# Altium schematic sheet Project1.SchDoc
size B; SheetNumber: 0; SheetTotal: 0
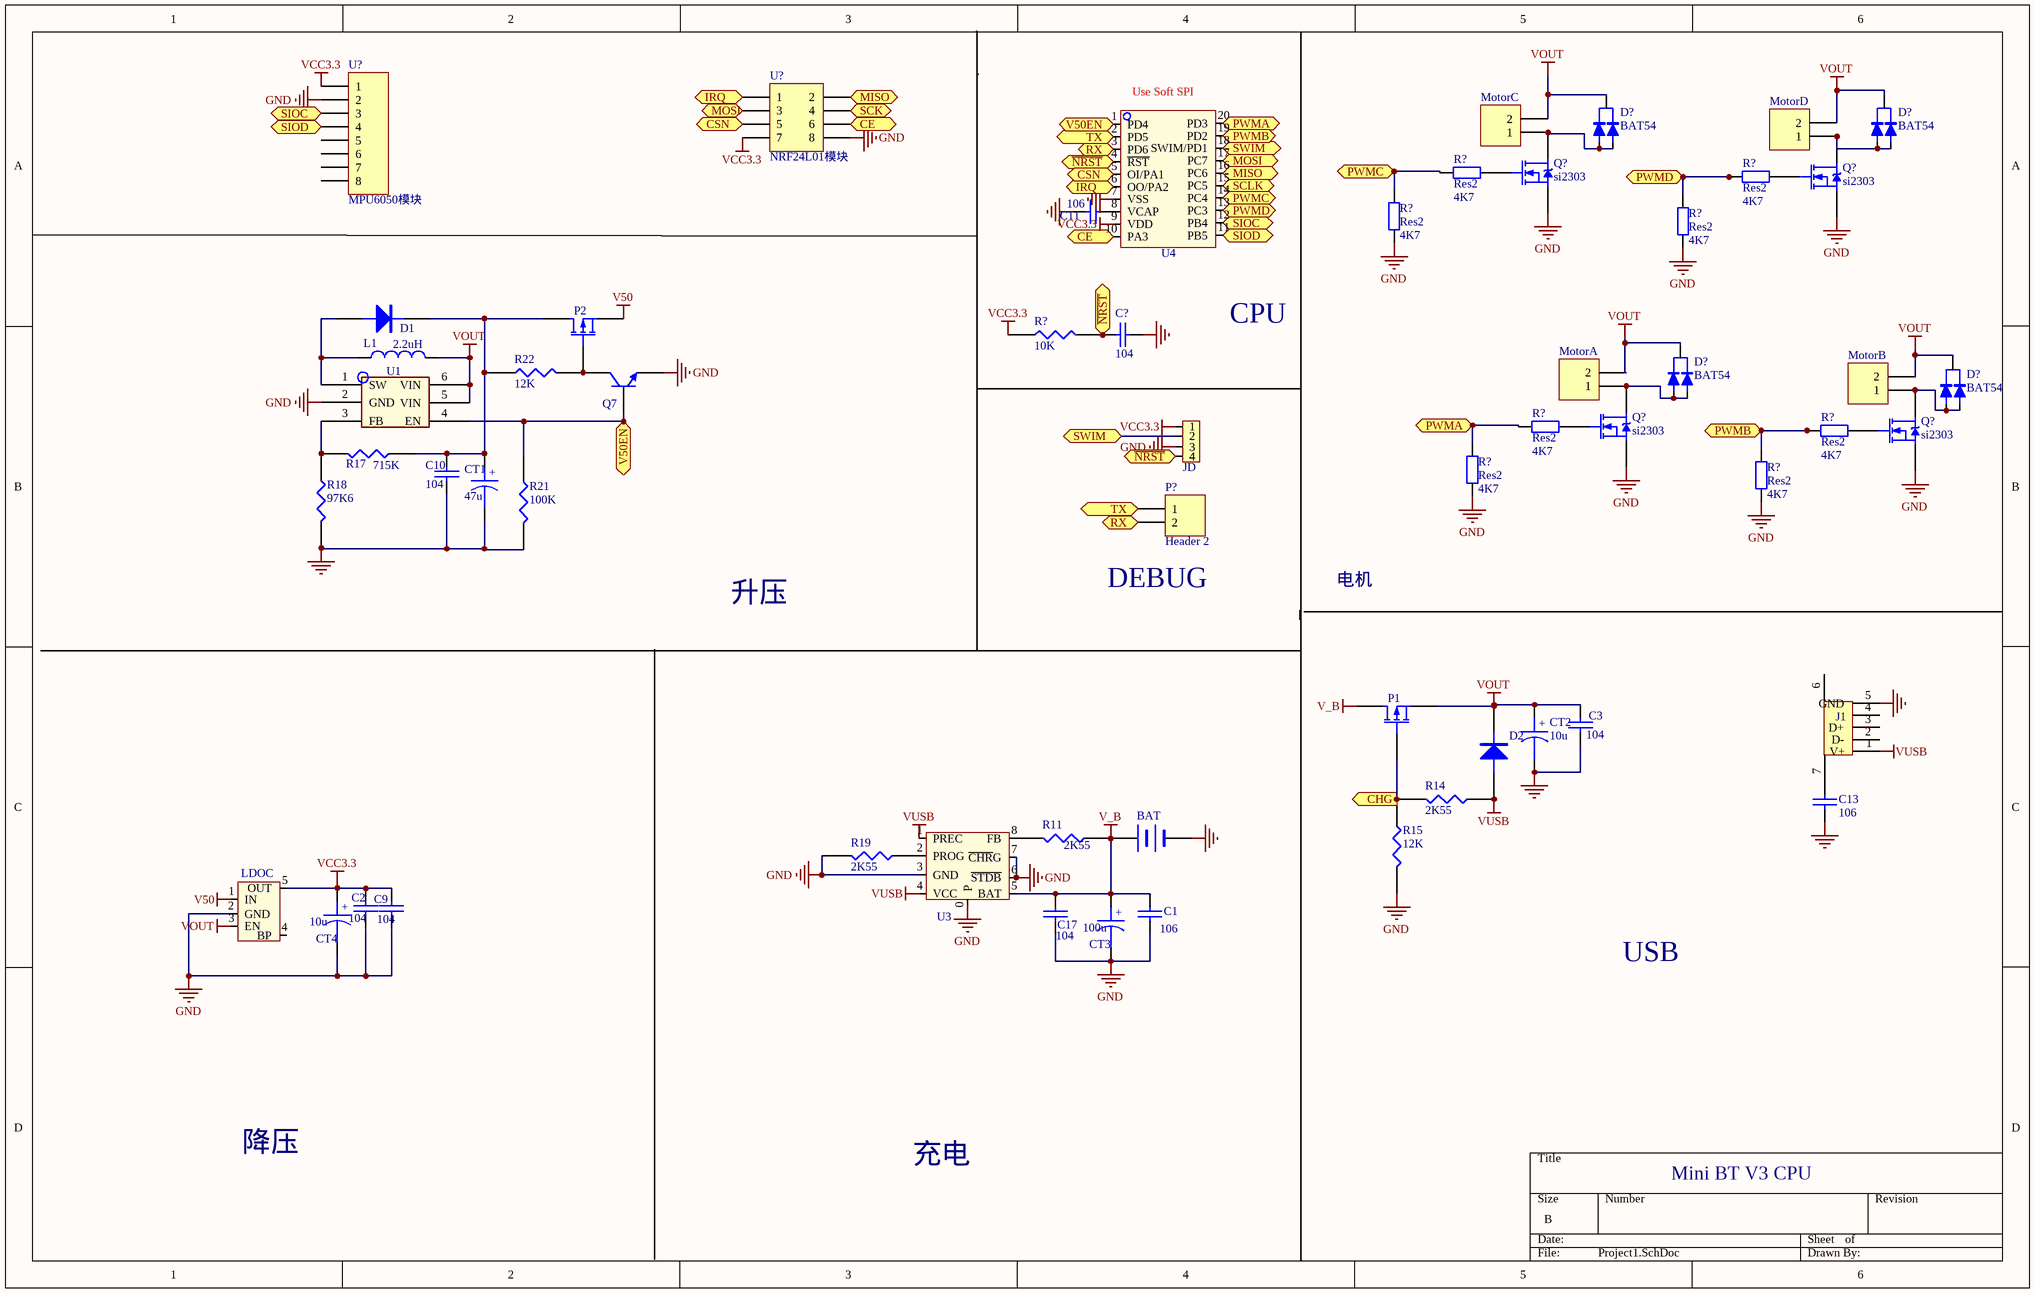
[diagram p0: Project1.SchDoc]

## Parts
(Parts that share a designator on the sheet are numbered #1, #2 ... from top to bottom, then left to right.)
BAT  (no value)  [BAT_2.0MM]
C1  106  [C0805]
C2  104  [0402_ADJ]
C3  104  [0402_ADJ]
C9  104  [0402_ADJ]
C10  104  [0402_ADJ]
C11  106  [C0805]
C13  106  [C0805]
C17  104  [0402_ADJ]
C?  104  [0402_ADJ]
CT1  47u  [C3216]
CT2  10u  [C3216]
CT3  100u  [C3528]
CT4  10u  [C3216]
D1  SS34  [DO214]  (value not drawn)
D2  SS34  [DO214]  (value not drawn)
D?#1  BAT54  [SOT-23-3]
D?#2  BAT54  [SOT-23-3]
D?#3  BAT54  [SOT-23-3]
D?#4  BAT54  [SOT-23-3]
J1  MicroUSB  [MicroUSB_modify]  (value not drawn)
JD  H4_G  [H4]  (value not drawn)
L1  2.2uH  [L5020]
LDOC  RT9193  [SOT23_5]  (value not drawn)
MotorA  Header 2  [HDR1X2]  (value not drawn)
MotorB  Header 2  [HDR1X2]  (value not drawn)
MotorC  Header 2  [HDR1X2]  (value not drawn)
MotorD  Header 2  [HDR1X2]  (value not drawn)
P1  PMOS_AO3401  [SOT23_AO3401]  (value not drawn)
P2  PMOS_AO3401  [SOT23_AO3401]  (value not drawn)
P?  Header 2  [HDR1X2]
Q7  2N3904  [SOT23_BJT]  (value not drawn)
Q?#1  si2303  [TO-220AB]
Q?#2  si2303  [TO-220AB]
Q?#3  si2303  [TO-220AB]
Q?#4  si2303  [TO-220AB]
R11  2K55  [0402_ADJ]
R14  2K55  [0402_ADJ]
R15  12K  [0402_ADJ]
R17  715K  [0402_ADJ]
R18  97K6  [0402_ADJ]
R19  2K55  [0402_ADJ]
R21  100K  [0402_ADJ]
R22  12K  [0402_ADJ]
R?#1  Res2  value 4K7  [AXIAL-0.4]
R?#2  Res2  value 4K7  [AXIAL-0.4]
R?#3  Res2  value 4K7  [AXIAL-0.4]
R?#4  Res2  value 4K7  [AXIAL-0.4]
R?#5  10K  [0402_ADJ]
R?#6  Res2  value 4K7  [AXIAL-0.4]
R?#7  Res2  value 4K7  [AXIAL-0.4]
R?#8  Res2  value 4K7  [AXIAL-0.4]
R?#9  Res2  value 4K7  [AXIAL-0.4]
U1  XR1151  [SOT-23-6L]  (value not drawn)
U3  CN3153  [SOIC8_39MM_TP4056]  (value not drawn)
U4  STM8S003F3P6_TSSOP20  [TSSOP20_44MM_065P]  (value not drawn)
U?#1  MPU6050模块  [HDR1X8]
U?#2  NRF24L01模块  [HDR2X4]

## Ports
CE, CHG (out), CSN, IRQ, MISO, MISO (bidir), MOSI, MOSI (bidir), PWMA, PWMB, PWMC, PWMD, RX (bidir), SCK, SCLK (bidir), SIOC, SIOD, SWIM, TX (bidir), V50EN (in), ~{NRST}

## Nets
GND: BAT.2(-) C1.2 C2.2 C3.2 C9.2 C10.2 C11.1 C13.1 C17.2 C?.2 CT1.2 CT2.2 CT3.2 CT4.2 J1.5(GND) JD.3 LDOC.2(GND) Q7.E Q?#1.S Q?#2.S Q?#3.S Q?#4.S R15.2 R18.2 R19.2 R21.2 R?#3.1 R?#4.1 R?#8.1 R?#9.1 U1.2(GND) U3.0(P) U3.3(GND) U3.6(~{STDB}) U3.7(~{CHR}G) U4.7(VSS) U?#1.2 U?#2.8
V50: LDOC.1(IN) P2.S
V_B: BAT.1(+) C1.1 C17.1 CT3.1 P1.D R11.1 U3.5(BAT)
VCC3.3: C2.1 C9.1 CT4.1 JD.1 LDOC.5(OUT) R?#5.1 U4.9(VDD) U?#1.1 U?#2.7
VOUT: C3.1 CT2.1 D2.2(K) D?#1.3 D?#2.3 D?#3.3 D?#4.3 L1.2 LDOC.3(EN) MotorA.2 MotorB.2 MotorC.2 MotorD.2 P1.S U1.5(VIN) U1.6(VIN)
VUSB: D2.1(A) J1.1(V+) R14.1 U3.1(PREC) U3.4(VCC)
CE: U4.10(PA3) U?#2.6 ; port CE
CHG: P1.G R14.2 R15.1 ; port CHG
CSN: U4.5(OI/PA1) U?#2.5 ; port CSN
IRQ: U4.6(OO/PA2) U?#2.1 ; port IRQ
MISO: U4.16(PC6) U?#2.2 ; port MISO
MOSI: U4.17(PC7) U?#2.3 ; port MOSI
~{NRST}: C?.1 JD.4 R?#5.2 U4.4(~{RST}) ; port ~{NRST}
PWMA: R?#6.1 R?#8.2 U4.20(PD3) ; port PWMA
PWMB: R?#7.1 R?#9.2 U4.19(PD2) ; port PWMB
PWMC: R?#1.1 R?#3.2 U4.14(PC4) ; port PWMC
PWMD: R?#2.1 R?#4.2 U4.13(PC3) ; port PWMD
RX: P?.2 U4.3(PD6) ; port RX
SCK: U?#2.4 ; port SCK
SCLK: U4.15(PC5) ; port SCLK
SIOC: U4.12(PB4) U?#1.3 ; port SIOC
SIOD: U4.11(PB5) U?#1.4 ; port SIOD
SWIM: JD.2 U4.18(SWIM/PD1) ; port SWIM
TX: P?.1 U4.2(PD5) ; port TX
V50EN: Q7.B R21.1 U1.4(EN) U4.1(PD4) ; port V50EN
NetC10_1: C10.1 CT1.1 D1.2(K) P2.D R17.1 R22.1
NetC11_2: C11.2 U4.8(VCAP)
NetC13_2: C13.2 J1.7(Shell)
NetD1_1: D1.1(A) L1.1 U1.1(SW)
NetD?#1_1: D?#1.1 D?#1.2 MotorC.1 Q?#1.D
NetD?#2_1: D?#2.1 D?#2.2 MotorD.1 Q?#2.D
NetD?#3_1: D?#3.1 D?#3.2 MotorA.1 Q?#3.D
NetD?#4_1: D?#4.1 D?#4.2 MotorB.1 Q?#4.D
NetP2_G: P2.G Q7.C R22.2
NetQ?#1_G: Q?#1.G R?#1.2
NetQ?#2_G: Q?#2.G R?#2.2
NetQ?#3_G: Q?#3.G R?#6.2
NetQ?#4_G: Q?#4.G R?#7.2
NetR11_2: R11.2 U3.8(FB)
NetR17_2: R17.2 R18.1 U1.3(FB)
NetR19_1: R19.1 U3.2(PROG)

Not connected (* = marked no-connect by the designer): J1 2(D-) 3(D+) 4(ID) 6(Shell); LDOC 4(BP); U?#1 5 6 7 8

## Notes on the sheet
- (near U4) Use Soft SPI
- CPU
- 升压
- (near P?) DEBUG
- 电机
- USB
- 降压
- 充电
- Mini BT V3 CPU

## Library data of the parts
BAT = BATTERY
C1-C3 C9-C11 C13 C17 C? = CAP: Capacitor
CT1-CT4 = CAPACITOR POL: Capacitor
D1 D2 = DIODE
D?#1-D?#4 = 2DIODE
L1 = Inductor: Code_IEC: 1005
MotorA MotorB MotorC MotorD P? = Header 2: Header, 2-Pin
Q7 = NPN: NPN General Purpose Amplifier
Q?#1-Q?#4 = MOSFET-N: N-Channel MOSFET; PackageDocument: 1995/1996
R11 R14 R15 R17-R19 R21 R22 R?#5 = RES1
R?#1-R?#4 R?#6-R?#9 = Res2: Resistor
U?#1 = Header 8: Header, 8-Pin
U?#2 = Header 4X2: Header, 4-Pin, Dual row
